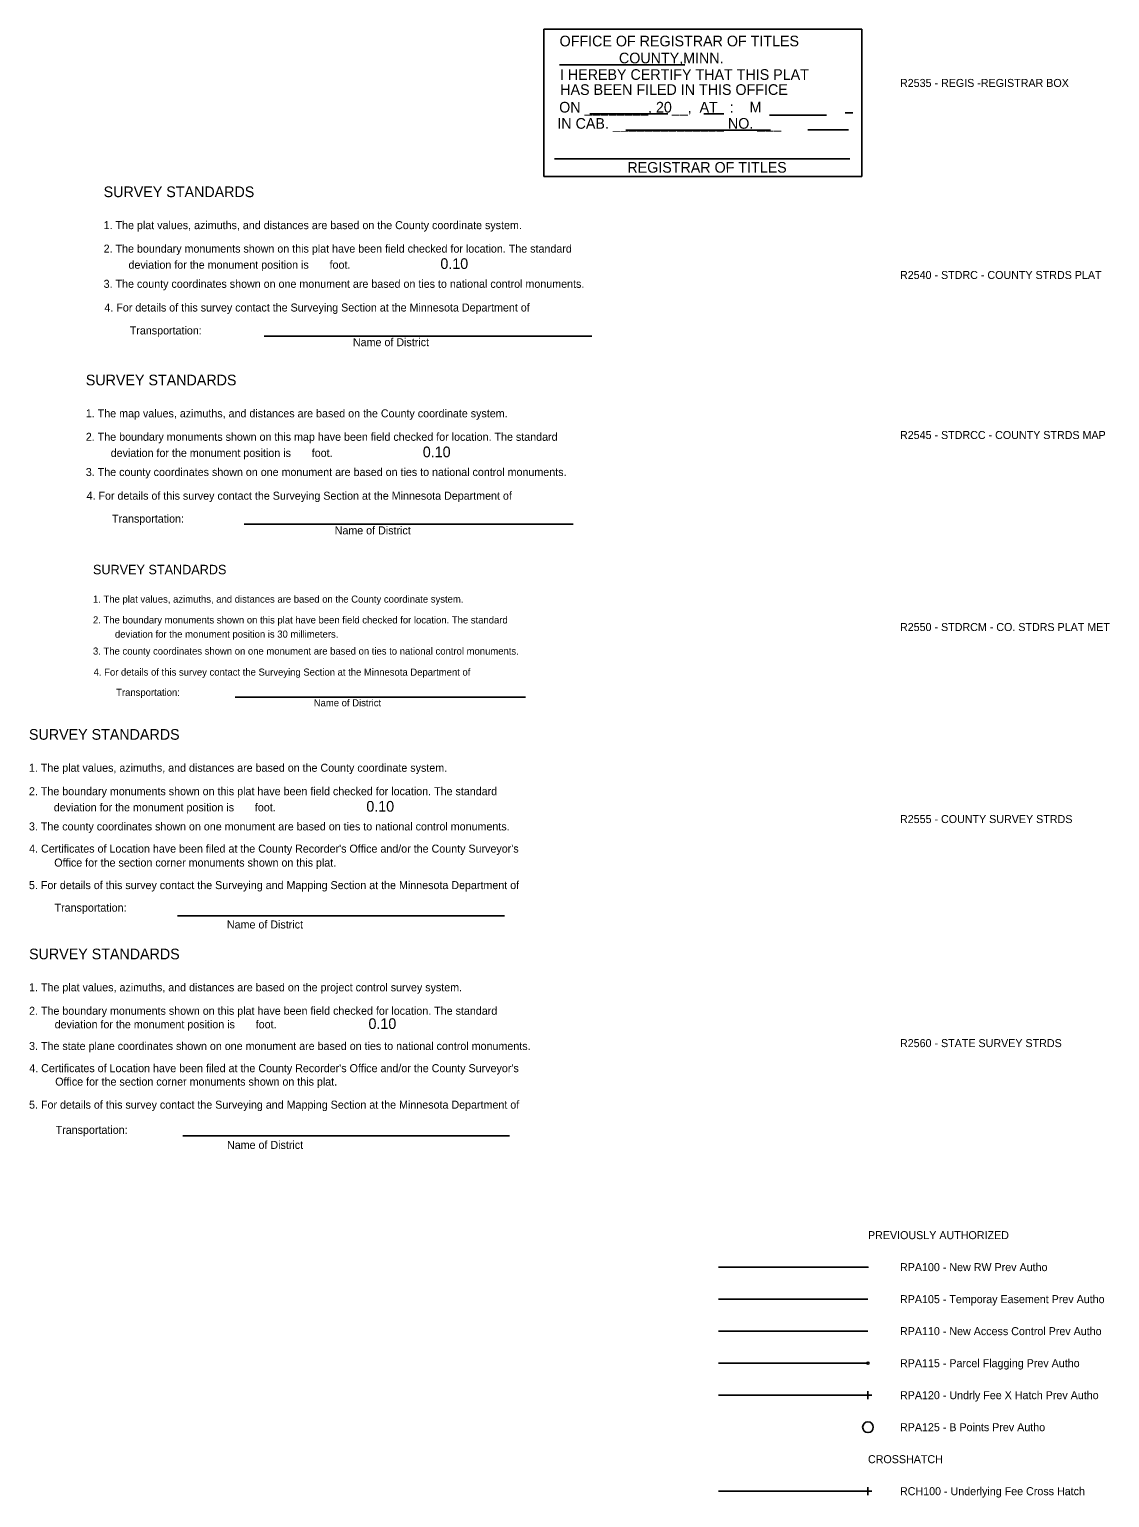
# Model space of a CAD drawing. Extents: x 2147712 to 2176316, y 2125036 to 2131746.
# Drawn here: x 2169675 to 2170688, y 2126934 to 2128310 of the extents above; entities that cross this region are included whole.
import ezdxf

# ---------------------------------------------------------------- set-up
doc = ezdxf.new("R2010")
doc.units = 0
for name, color, linetype in [('ACC PREV AUTH', 7, 'Continuous'), ('B PNTS PREV AUTH', 7, 'Continuous'), ('Default', 7, 'Continuous'), ('NRW PREV AUTH', 7, 'Continuous'), ('PAR FLAG PREV AUTH', 7, 'Continuous'), ('PLAT INFO', 7, 'Continuous'), ('TMP ESMT PREV AUTH', 7, 'Continuous'), ('UNDRLY FEE', 7, 'Continuous'), ('UNDRLY FEE PREV AUTH', 7, 'Continuous')]:
    doc.layers.add(name, color=color, linetype=linetype)

msp = doc.modelspace()

# ---------------------------------------------------------------- linework, layer by layer
at = {"layer": 'ACC PREV AUTH'}
msp.add_line((2170461.3, 2127089.7), (2170321.3, 2127089.7), dxfattribs=at)
at = {"layer": 'B PNTS PREV AUTH'}
msp.add_circle((2170461.3, 2126999.7), 5, dxfattribs=at)
at = {"layer": 'Default'}
for p, q in [((2170465, 2127029.7), (2170457.5, 2127029.7)), ((2170461.3, 2127033.5), (2170461.3, 2127026)), ((2170465, 2126939.7), (2170457.5, 2126939.7)), ((2170461.3, 2126943.5), (2170461.3, 2126936))]:
    msp.add_line(p, q, dxfattribs=at)
at = {"layer": 'NRW PREV AUTH'}
for p, q in [((2170461.3, 2127149.7), (2170321.3, 2127149.7)), ((2170461.2, 2127149.5), (2170461.4, 2127149.9)), ((2170461.2, 2127149.9), (2170461.4, 2127149.5))]:
    msp.add_line(p, q, dxfattribs=at)
at = {"layer": 'PAR FLAG PREV AUTH'}
msp.add_line((2170461.3, 2127059.7), (2170321.3, 2127059.7), dxfattribs=at)
msp.add_circle((2170461.3, 2127059.7), 1, dxfattribs=at)
at = {"layer": 'PLAT INFO'}
for p, q in [((2170157.6, 2128171.9), (2170157.5, 2128310)), ((2170157.5, 2128310), (2170455.7, 2128310)), ((2170455.7, 2128171.9), (2170455.7, 2128310)), ((2170172.2, 2128276.7), (2170289.7, 2128276.7)), ((2170273.6, 2128230.9), (2170200.7, 2128230.9)), ((2170307.6, 2128230.7), (2170326.3, 2128230.7)), ((2170369.1, 2128229.5), (2170422.3, 2128229.5)), ((2170447.1, 2128231.6), (2170439.8, 2128231.6)), ((2170234.3, 2128215.4), (2170369.9, 2128215.4)), ((2170404.8, 2128215.7), (2170443.1, 2128215.7)), ((2170167.4, 2128188.6), (2170444.2, 2128188.6)), ((2170157.6, 2128171.9), (2170455.7, 2128171.9)), ((2169895.4, 2128022.5), (2170202.4, 2128022.5)), ((2169876.6, 2127846.1), (2170184.9, 2127846.1)), ((2169868.2, 2127683.9), (2170140.2, 2127683.9)), ((2169814.1, 2127479.1), (2170120.7, 2127479.1)), ((2169819.1, 2127272.9), (2170125.5, 2127272.9))]:
    msp.add_line(p, q, dxfattribs=at)
at = {"layer": 'TMP ESMT PREV AUTH'}
msp.add_line((2170461.3, 2127119.7), (2170321.3, 2127119.7), dxfattribs=at)
at = {"layer": 'UNDRLY FEE'}
msp.add_line((2170461.3, 2126939.7), (2170321.3, 2126939.7), dxfattribs=at)
at = {"layer": 'UNDRLY FEE PREV AUTH'}
msp.add_line((2170461.3, 2127029.7), (2170321.3, 2127029.7), dxfattribs=at)

# ---------------------------------------------------------------- texts
at = {"layer": 'Default'}
for s, p in [('R2535 - REGIS -REGISTRAR BOX', (2170491.3, 2128256)), ('R2540 - STDRC - COUNTY STRDS PLAT', (2170491.3, 2128076)), ('R2545 - STDRCC - COUNTY STRDS MAP', (2170491.3, 2127926)), ('R2550 - STDRCM - CO. STDRS PLAT MET', (2170491.3, 2127746)), ('R2555 - COUNTY SURVEY STRDS', (2170491.3, 2127566)), ('R2560 - STATE SURVEY STRDS', (2170491.3, 2127356)), ('PREVIOUSLY AUTHORIZED', (2170461.3, 2127176)), ('RPA100 - New RW Prev Autho', (2170491.3, 2127146)), ('RPA105 - Temporay Easement Prev Autho', (2170491.3, 2127116)), ('RPA110 - New Access Control Prev Autho', (2170491.3, 2127086)), ('RPA125 - B Points Prev Autho', (2170491.3, 2126996)), ('CROSSHATCH', (2170461.3, 2126966)), ('RCH100 - Underlying Fee Cross Hatch', (2170491.3, 2126936))]:
    msp.add_text(s, height=7.5, dxfattribs=at).set_placement(p)
at = {"layer": 'PAR FLAG PREV AUTH'}
for s, p in [('RPA115 - Parcel Flagging Prev Autho', (2170491.3, 2127056)), ('RPA120 - Undrly Fee X Hatch Prev Autho', (2170491.3, 2127026))]:
    msp.add_text(s, height=7.5, dxfattribs=at).set_placement(p)
at = {"layer": 'PLAT INFO'}
for s, p in [('OFFICE OF REGISTRAR OF TITLES ', (2170172.3, 2128294)), ('               COUNTY,MINN.', (2170172.2, 2128278.1)), ('I HEREBY CERTIFY THAT THIS PLAT', (2170172.6, 2128262.6)), ('HAS BEEN FILED IN THIS OFFICE', (2170172.9, 2128248.5)), ('ON ________, 20__,  AT   :    M', (2170171.9, 2128232)), ('IN CAB. ______________ NO. ___', (2170170.2, 2128216.8)), ('REGISTRAR OF TITLES', (2170235.8, 2128175.6))]:
    msp.add_text(s, height=10, rotation=0.0124, dxfattribs=at).set_placement(p)
for s, height, p in [('SURVEY STANDARDS', 10, (2169745, 2128152.7)), ('1. The plat values, azimuths, and distances are based on the County coordinate system.', 7.5, (2169745, 2128122.7)), ('2. The boundary monuments shown on this plat have been field checked for location. The standard', 7.5, (2169745, 2128100.7)), ('0.10', 10, (2170060.6, 2128085.4)), ('deviation for the monument position is       foot.', 7.5, (2169768.3, 2128085.6)), ('3. The county coordinates shown on one monument are based on ties to national control monuments.', 7.5, (2169745, 2128067.7)), ('4. For details of this survey contact the Surveying Section at the Minnesota Department of', 7.5, (2169745.7, 2128045.5)), ('Transportation:', 7.5, (2169769.5, 2128024)), ('Name of District', 7.5, (2169978.6, 2128013)), ('SURVEY STANDARDS', 10, (2169728.3, 2127976.3)), ('1. The map values, azimuths, and distances are based on the County coordinate system.', 7.5, (2169728.3, 2127946.3)), ('2. The boundary monuments shown on this map have been field checked for location. The standard', 7.5, (2169728.3, 2127924.3)), ('deviation for the monument position is       foot.', 7.5, (2169751.6, 2127909.2)), ('0.10', 10, (2170044.1, 2127908.9)), ('3. The county coordinates shown on one monument are based on ties to national control monuments.', 7.5, (2169728.3, 2127891.3)), ('4. For details of this survey contact the Surveying Section at the Minnesota Department of', 7.5, (2169729, 2127869.1)), ('Transportation:', 7.5, (2169752.8, 2127847.6)), ('Name of District', 7.5, (2169961.5, 2127836.6)), ('SURVEY STANDARDS', 8.858, (2169735, 2127799.2)), ('1. The plat values, azimuths, and distances are based on the County coordinate system.', 6.644, (2169735, 2127772.6)), ('2. The boundary monuments shown on this plat have been field checked for location. The standard', 6.644, (2169735, 2127753.1)), ('deviation for the monument position is 30 millimeters.', 6.644, (2169755.6, 2127739.8)), ('3. The county coordinates shown on one monument are based on ties to national control monuments.', 6.644, (2169735, 2127723.9)), ('4. For details of this survey contact the Surveying Section at the Minnesota Department of', 6.644, (2169735.6, 2127704.2)), ('Transportation:', 6.644, (2169756.7, 2127685.2)), ('Name of District', 6.644, (2169941.9, 2127675.4)), ('SURVEY STANDARDS', 10, (2169675, 2127644.1)), ('1. The plat values, azimuths, and distances are based on the County coordinate system.', 7.5, (2169675, 2127614.1)), ('2. The boundary monuments shown on this plat have been field checked for location. The standard', 7.5, (2169675, 2127592.1)), ('0.10', 10, (2169991.2, 2127576.7)), ('deviation for the monument position is       foot.', 7.5, (2169698.3, 2127577)), ('3. The county coordinates shown on one monument are based on ties to national control monuments.', 7.5, (2169675, 2127559.1)), ("4. Certificates of Location have been filed at the County Recorder's Office and/or the County Surveyor's", 7.5, (2169675.2, 2127538.3)), ('Office for the section corner monuments shown on this plat.', 7.5, (2169698.7, 2127525.2)), ('5. For details of this survey contact the Surveying and Mapping Section at the Minnesota Department of', 7.5, (2169675, 2127504.1)), ('Transportation:', 7.5, (2169699, 2127483)), ('Name of District', 7.5, (2169860.5, 2127467.2)), ('SURVEY STANDARDS', 10, (2169675.1, 2127438.3)), ('1. The plat values, azimuths, and distances are based on the project control survey system.', 7.5, (2169675.1, 2127408.3)), ('2. The boundary monuments shown on this plat have been field checked for location. The standard', 7.5, (2169675.1, 2127386.3)), ('deviation for the monument position is       foot.', 7.5, (2169699.1, 2127373.6)), ('0.10', 10, (2169993.2, 2127373)), ('3. The state plane coordinates shown on one monument are based on ties to national control monuments.', 7.5, (2169675.1, 2127353.3)), ("4. Certificates of Location have been filed at the County Recorder's Office and/or the County Surveyor's", 7.5, (2169675.3, 2127332.5)), ('Office for the section corner monuments shown on this plat.', 7.5, (2169699.6, 2127319.9)), ('5. For details of this survey contact the Surveying and Mapping Section at the Minnesota Department of', 7.5, (2169675.1, 2127298.3)), ('Transportation:', 7.5, (2169700, 2127274.7)), ('Name of District', 7.5, (2169860.6, 2127260.6))]:
    msp.add_text(s, height=height, dxfattribs=at).set_placement(p)

doc.saveas('drawing.dxf')
